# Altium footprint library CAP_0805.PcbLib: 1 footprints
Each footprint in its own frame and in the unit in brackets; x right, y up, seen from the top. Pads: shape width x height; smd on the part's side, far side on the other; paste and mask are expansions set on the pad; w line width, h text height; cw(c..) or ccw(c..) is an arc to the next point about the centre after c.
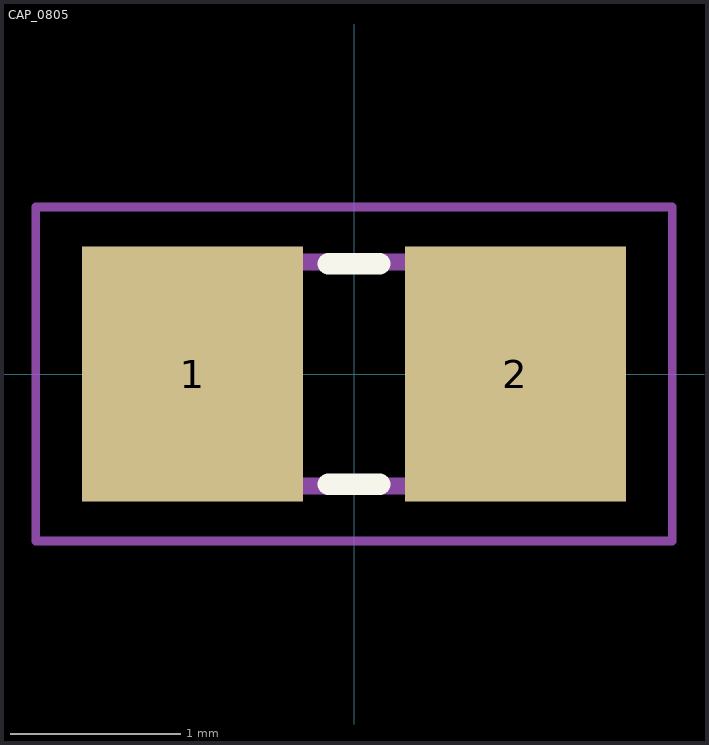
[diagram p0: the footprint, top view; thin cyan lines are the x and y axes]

## CAP_0805 [mm]
pads (2):
  rect 1.3x1.5 smd: 1(-0.95,0) 2(0.95,0)
Top Overlay:
  lines w0.127: -0.15,-0.65 0.15,-0.65 ; -0.15,0.65 0.15,0.65
Mechanical 13:
  region: -0.342,-0.724 -1.092,-0.724 -1.092,0.726 -0.342,0.726
  region: 1.106,-0.724 0.356,-0.724 0.356,0.726 1.106,0.726
  lines w0.102: -0.381,0.66 0.381,0.66 ; -0.356,-0.66 0.381,-0.66
Mechanical 15:
  lines w0.051: -1.873,-0.983 1.873,-0.983 1.873,0.983 -1.873,0.983 -1.873,-0.983
3D body "CAP_0805.STEP": height 0.72, standoff -0.72, extent -1,-0.625 1,0.625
